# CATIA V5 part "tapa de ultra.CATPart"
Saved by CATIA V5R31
Part number: tapa de ultra
Bounding box of the stored display mesh (mm): x -40 to 40, y 0 to 163.2, z 0 to 3.3
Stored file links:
  C:\Users\189361\Desktop\piezas del comedero\piezas del comedero\tapa de ultra.CATPart
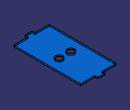
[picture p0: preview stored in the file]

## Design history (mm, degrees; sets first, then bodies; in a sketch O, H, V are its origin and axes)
Body1 (main body)
  Sketch1 on xy-plane, origin (0, 0, 0), H (1, 0, 0), V (0, 1, 0)
    point P1 (0, 0)
    line L1 (0, 0) -> (-7.65, 0)
    point P2 (-7.65, 0)
    line L2 (-7.65, 0) -> (-7.65, 6.6)
    point P3 (-7.65, 6.6)
    line L3 (-7.65, 6.6) -> (-40, 6.6)
    point P4 (-40, 6.6)
    line L4 (-40, 6.6) -> (-40, 156.6)
    point P5 (-40, 156.6)
    line L5 (-40, 156.6) -> (-7.65, 156.6)
    point P6 (-7.65, 156.6)
    line L6 (-7.65, 156.6) -> (-7.65, 163.2)
    point P7 (-7.65, 163.2)
    line L7 (-7.65, 163.2) -> (0, 163.2)
    point P8 (0, 163.2)
    circle A1 centre (-13, 81.6) radius 8
    point P9 (-13, 81.6)
    point P10 (0, 0)
    point P11 (0, 0)
    point P12 (7.65, 0)
    point P13 (7.65, 6.6)
    point P14 (40, 6.6)
    point P15 (40, 156.6)
    point P16 (7.65, 156.6)
    point P17 (7.65, 163.2)
    point P18 (0, 163.2)
    line L8 (0, 0) -> (7.65, 0)
    line L9 (7.65, 0) -> (7.65, 6.6)
    line L10 (7.65, 6.6) -> (40, 6.6)
    line L11 (40, 6.6) -> (40, 156.6)
    line L12 (40, 156.6) -> (7.65, 156.6)
    line L13 (7.65, 156.6) -> (7.65, 163.2)
    line L14 (7.65, 163.2) -> (0, 163.2)
    circle A2 centre (13, 81.6) radius 8
    length L1 = 7.65
    length L2 = 6.6
    length L4 = 150
    distance V L4 = 40
    radius A1 = 8
    distance V P9 = 13
    distance L10 P9 = 75
    coincidence: P1 V, P6 L2, P8 V, L1 H, P1 P11, P8 P18
    horizontal: L1 H, L3 H, L5 H, L7 H
    vertical: L2 V, L4 V, L6 V
    equal size: L6 L2, L1 L7
    symmetry: O P10 V, P1 P11 V, P2 P12 V, P3 P13 V, P4 P14 V, P5 P15 V, P6 P16 V, P7 P17 V, P8 P18 V, L1 L8 V, L2 L9 V, L3 L10 V, L4 L11 V, L5 L12 V, L6 L13 V, L7 L14 V, A1 A2 V
  Pad1: profile Sketch1, direction (0, 0, 1), length 3.3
